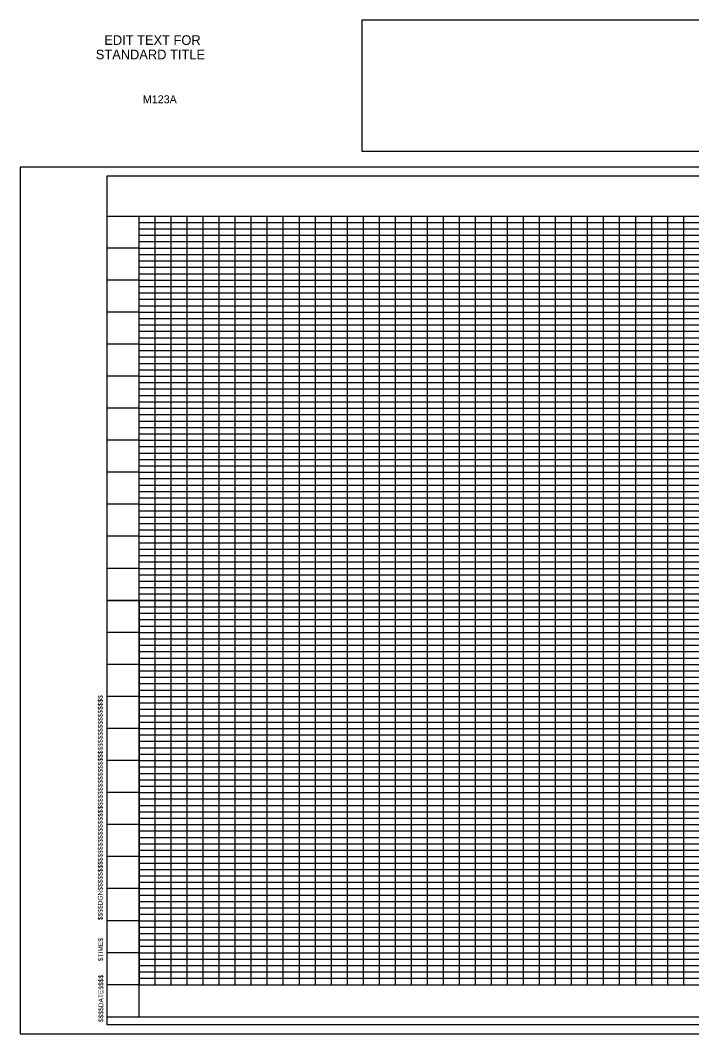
# Model space of a CAD drawing. Extents: x -27 to 395, y -3 to 314.
# Drawn here: x -27.1 to 182.5, y -2.8 to 313.6 of the extents above; entities that cross this region are included whole.
import ezdxf

# ---------------------------------------------------------------- set-up
doc = ezdxf.new("R2010")
doc.units = 0
for name, color, linetype in [('D_CFL_Clip_Boundary_1', 7, 'Continuous'), ('D_CFL_Clip_Boundary_2', 7, 'Continuous'), ('D_CFL_Sheet_Border_ PlotShape', 7, 'Continuous'), ('D_CFL_Sheet_Border_Base', 7, 'Continuous'), ('D_CFL_Sheet_Border_Plan_Plan', 7, 'Continuous'), ('D_CFL_Sheet_Border_PnP', 7, 'Continuous'), ('D_CFL_Sheet_Border_Profile', 7, 'Continuous')]:
    doc.layers.add(name, color=color, linetype=linetype)

msp = doc.modelspace()

# ---------------------------------------------------------------- linework, layer by layer
at = {"layer": 'D_CFL_Clip_Boundary_1'}
msp.add_lwpolyline([(0, 265), (326.25, 265), (326.25, 255), (390, 255), (390, 132.5), (0, 132.5)], close=True, dxfattribs=at)
at = {"layer": 'D_CFL_Clip_Boundary_2'}
msp.add_lwpolyline([(380, 132.5), (10, 132.5), (10, 12.5), (380, 12.5)], close=True, dxfattribs=at)
at = {"layer": 'D_CFL_Sheet_Border_ PlotShape'}
msp.add_line((-27.13, -2.8), (-27.13, -2.8), dxfattribs=at)
msp.add_lwpolyline([(-27.13, -2.8), (395.49, -2.8), (395.49, 267.8), (-27.13, 267.8)], close=True, dxfattribs=at)
at = {"layer": 'D_CFL_Sheet_Border_Base'}
for points in [[(79.54, 272.77), (390, 272.77), (390, 313.62), (79.54, 313.62)], [(0, 265), (390, 265), (390, 0), (0, 0)]]:
    msp.add_lwpolyline(points, close=True, dxfattribs=at)
at = {"layer": 'D_CFL_Sheet_Border_Plan_Plan'}
msp.add_line((0, 132.5), (390, 132.5), dxfattribs=at)
at = {"layer": 'D_CFL_Sheet_Border_PnP'}
for p, q in [((0, 132.5), (390, 132.5)), ((10, 2.5), (10, 132.5)), ((10, 130.5), (380, 130.5)), ((15, 12.5), (15, 132.5)), ((20, 12.5), (20, 132.5)), ((25, 12.5), (25, 132.5)), ((30, 12.5), (30, 132.5)), ((35, 12.5), (35, 132.5)), ((40, 12.5), (40, 132.5)), ((45, 12.5), (45, 132.5)), ((50, 12.5), (50, 132.5)), ((55, 12.5), (55, 132.5)), ((60, 12.5), (60, 132.5)), ((65, 12.5), (65, 132.5)), ((70, 12.5), (70, 132.5)), ((75, 12.5), (75, 132.5)), ((80, 12.5), (80, 132.5)), ((85, 12.5), (85, 132.5)), ((90, 12.5), (90, 132.5)), ((95, 12.5), (95, 132.5)), ((100, 12.5), (100, 132.5)), ((105, 12.5), (105, 132.5)), ((110, 12.5), (110, 132.5)), ((115, 12.5), (115, 132.5)), ((120, 12.5), (120, 132.5)), ((125, 12.5), (125, 132.5)), ((130, 12.5), (130, 132.5)), ((135, 12.5), (135, 132.5)), ((140, 12.5), (140, 132.5)), ((145, 12.5), (145, 132.5)), ((150, 12.5), (150, 132.5)), ((155, 12.5), (155, 132.5)), ((160, 12.5), (160, 132.5)), ((165, 12.5), (165, 132.5)), ((170, 12.5), (170, 132.5)), ((175, 12.5), (175, 132.5)), ((180, 12.5), (180, 132.5)), ((10, 128.5), (380, 128.5)), ((10, 126.5), (380, 126.5)), ((10, 124.5), (380, 124.5)), ((10, 122.5), (0, 122.5)), ((10, 122.5), (380, 122.5)), ((10, 120.5), (380, 120.5)), ((10, 118.5), (380, 118.5)), ((10, 116.5), (380, 116.5)), ((10, 114.5), (380, 114.5)), ((10, 112.5), (0, 112.5)), ((10, 112.5), (380, 112.5)), ((10, 110.5), (380, 110.5)), ((10, 108.5), (380, 108.5)), ((10, 106.5), (380, 106.5)), ((10, 104.5), (380, 104.5)), ((10, 102.5), (0, 102.5)), ((10, 102.5), (380, 102.5)), ((10, 100.5), (380, 100.5)), ((10, 98.5), (380, 98.5)), ((10, 96.5), (380, 96.5)), ((10, 92.5), (0, 92.5)), ((10, 94.5), (380, 94.5)), ((10, 92.5), (380, 92.5)), ((10, 90.5), (380, 90.5)), ((10, 88.5), (380, 88.5)), ((10, 86.5), (380, 86.5)), ((10, 82.5), (0, 82.5)), ((10, 84.5), (380, 84.5)), ((10, 82.5), (380, 82.5)), ((10, 80.5), (380, 80.5)), ((10, 78.5), (380, 78.5)), ((10, 76.5), (380, 76.5)), ((10, 74.5), (380, 74.5)), ((10, 72.5), (0, 72.5)), ((10, 72.5), (380, 72.5)), ((10, 70.5), (380, 70.5)), ((10, 68.5), (380, 68.5)), ((10, 66.5), (380, 66.5)), ((10, 64.5), (380, 64.5)), ((10, 62.5), (0, 62.5)), ((10, 62.5), (380, 62.5)), ((10, 60.5), (380, 60.5)), ((10, 58.5), (380, 58.5)), ((10, 56.5), (380, 56.5)), ((10, 54.5), (380, 54.5)), ((10, 52.5), (0, 52.5)), ((10, 52.5), (380, 52.5)), ((10, 50.5), (380, 50.5)), ((10, 48.5), (380, 48.5)), ((10, 46.5), (380, 46.5)), ((10, 44.5), (380, 44.5)), ((10, 42.5), (0, 42.5)), ((10, 42.5), (380, 42.5)), ((10, 40.5), (380, 40.5)), ((10, 38.5), (380, 38.5)), ((10, 36.5), (380, 36.5)), ((10, 32.5), (0, 32.5)), ((10, 34.5), (380, 34.5)), ((10, 32.5), (380, 32.5)), ((10, 30.5), (380, 30.5)), ((10, 28.5), (380, 28.5)), ((10, 26.5), (380, 26.5)), ((10, 22.5), (0, 22.5)), ((10, 24.5), (380, 24.5)), ((10, 22.5), (380, 22.5)), ((10, 20.5), (380, 20.5)), ((10, 18.5), (380, 18.5)), ((10, 16.5), (380, 16.5)), ((10, 14.5), (380, 14.5)), ((10, 12.5), (0, 12.5)), ((10, 12.5), (380, 12.5)), ((0, 2.5), (390, 2.5))]:
    msp.add_line(p, q, dxfattribs=at)
at = {"layer": 'D_CFL_Sheet_Border_Profile'}
for p, q in [((0, 252.5), (390, 252.5)), ((10, 2.5), (10, 252.5)), ((10, 250.5), (380, 250.5)), ((15, 12.5), (15, 252.5)), ((20, 12.5), (20, 252.5)), ((25, 12.5), (25, 252.5)), ((30, 12.5), (30, 252.5)), ((35, 12.5), (35, 252.5)), ((40, 12.5), (40, 252.5)), ((45, 12.5), (45, 252.5)), ((50, 12.5), (50, 252.5)), ((55, 12.5), (55, 252.5)), ((60, 12.5), (60, 252.5)), ((65, 12.5), (65, 252.5)), ((70, 12.5), (70, 252.5)), ((75, 12.5), (75, 252.5)), ((80, 12.5), (80, 252.5)), ((85, 12.5), (85, 252.5)), ((90, 12.5), (90, 252.5)), ((95, 12.5), (95, 252.5)), ((100, 12.5), (100, 252.5)), ((105, 12.5), (105, 252.5)), ((110, 12.5), (110, 252.5)), ((115, 12.5), (115, 252.5)), ((120, 12.5), (120, 252.5)), ((125, 12.5), (125, 252.5)), ((130, 12.5), (130, 252.5)), ((135, 12.5), (135, 252.5)), ((140, 12.5), (140, 252.5)), ((145, 12.5), (145, 252.5)), ((150, 12.5), (150, 252.5)), ((155, 12.5), (155, 252.5)), ((160, 12.5), (160, 252.5)), ((165, 12.5), (165, 252.5)), ((170, 12.5), (170, 252.5)), ((175, 12.5), (175, 252.5)), ((180, 12.5), (180, 252.5)), ((10, 248.5), (380, 248.5)), ((10, 246.5), (380, 246.5)), ((10, 244.5), (380, 244.5)), ((10, 242.5), (0, 242.5)), ((10, 242.5), (380, 242.5)), ((10, 240.5), (380, 240.5)), ((10, 238.5), (380, 238.5)), ((10, 236.5), (380, 236.5)), ((10, 234.5), (380, 234.5)), ((10, 232.5), (0, 232.5)), ((10, 232.5), (380, 232.5)), ((10, 230.5), (380, 230.5)), ((10, 228.5), (380, 228.5)), ((10, 226.5), (380, 226.5)), ((10, 222.5), (0, 222.5)), ((10, 224.5), (380, 224.5)), ((10, 222.5), (380, 222.5)), ((10, 220.5), (380, 220.5)), ((10, 218.5), (380, 218.5)), ((10, 216.5), (380, 216.5)), ((10, 212.5), (0, 212.5)), ((10, 214.5), (380, 214.5)), ((10, 212.5), (380, 212.5)), ((10, 210.5), (380, 210.5)), ((10, 208.5), (380, 208.5)), ((10, 206.5), (380, 206.5)), ((10, 204.5), (380, 204.5)), ((10, 202.5), (0, 202.5)), ((10, 202.5), (380, 202.5)), ((10, 200.5), (380, 200.5)), ((10, 198.5), (380, 198.5)), ((10, 196.5), (380, 196.5)), ((10, 194.5), (380, 194.5)), ((10, 192.5), (0, 192.5)), ((10, 192.5), (380, 192.5)), ((10, 190.5), (380, 190.5)), ((10, 188.5), (380, 188.5)), ((10, 186.5), (380, 186.5)), ((10, 184.5), (380, 184.5)), ((10, 182.5), (0, 182.5)), ((10, 182.5), (380, 182.5)), ((10, 180.5), (380, 180.5)), ((10, 178.5), (380, 178.5)), ((10, 176.5), (380, 176.5)), ((10, 174.5), (380, 174.5)), ((10, 172.5), (0, 172.5)), ((10, 172.5), (380, 172.5)), ((10, 170.5), (380, 170.5)), ((10, 168.5), (380, 168.5)), ((10, 166.5), (380, 166.5)), ((10, 162.5), (0, 162.5)), ((10, 164.5), (380, 164.5)), ((10, 162.5), (380, 162.5)), ((10, 160.5), (380, 160.5)), ((10, 158.5), (380, 158.5)), ((10, 156.5), (380, 156.5)), ((10, 152.5), (0, 152.5)), ((10, 154.5), (380, 154.5)), ((10, 152.5), (380, 152.5)), ((10, 150.5), (380, 150.5)), ((10, 148.5), (380, 148.5)), ((10, 146.5), (380, 146.5)), ((10, 142.5), (0, 142.5)), ((10, 144.5), (380, 144.5)), ((10, 142.5), (380, 142.5)), ((10, 140.5), (380, 140.5)), ((10, 138.5), (380, 138.5)), ((10, 136.5), (380, 136.5)), ((10, 134.5), (380, 134.5)), ((10, 132.5), (0, 132.5)), ((10, 132.5), (380, 132.5)), ((10, 130.5), (380, 130.5)), ((10, 128.5), (380, 128.5)), ((10, 126.5), (380, 126.5)), ((10, 124.5), (380, 124.5)), ((10, 122.5), (0, 122.5)), ((10, 122.5), (380, 122.5)), ((10, 120.5), (380, 120.5)), ((10, 118.5), (380, 118.5)), ((10, 116.5), (380, 116.5)), ((10, 114.5), (380, 114.5)), ((10, 112.5), (0, 112.5)), ((10, 112.5), (380, 112.5)), ((10, 110.5), (380, 110.5)), ((10, 108.5), (380, 108.5)), ((10, 106.5), (380, 106.5)), ((10, 104.5), (380, 104.5)), ((10, 102.5), (0, 102.5)), ((10, 102.5), (380, 102.5)), ((10, 100.5), (380, 100.5)), ((10, 98.5), (380, 98.5)), ((10, 96.5), (380, 96.5)), ((10, 92.5), (0, 92.5)), ((10, 94.5), (380, 94.5)), ((10, 92.5), (380, 92.5)), ((10, 90.5), (380, 90.5)), ((10, 88.5), (380, 88.5)), ((10, 86.5), (380, 86.5)), ((10, 82.5), (0, 82.5)), ((10, 84.5), (380, 84.5)), ((10, 82.5), (380, 82.5)), ((10, 80.5), (380, 80.5)), ((10, 78.5), (380, 78.5)), ((10, 76.5), (380, 76.5)), ((10, 74.5), (380, 74.5)), ((10, 72.5), (0, 72.5)), ((10, 72.5), (380, 72.5)), ((10, 70.5), (380, 70.5)), ((10, 68.5), (380, 68.5)), ((10, 66.5), (380, 66.5)), ((10, 64.5), (380, 64.5)), ((10, 62.5), (0, 62.5)), ((10, 62.5), (380, 62.5)), ((10, 60.5), (380, 60.5)), ((10, 58.5), (380, 58.5)), ((10, 56.5), (380, 56.5)), ((10, 54.5), (380, 54.5)), ((10, 52.5), (0, 52.5)), ((10, 52.5), (380, 52.5)), ((10, 50.5), (380, 50.5)), ((10, 48.5), (380, 48.5)), ((10, 46.5), (380, 46.5)), ((10, 44.5), (380, 44.5)), ((10, 42.5), (0, 42.5)), ((10, 42.5), (380, 42.5)), ((10, 40.5), (380, 40.5)), ((10, 38.5), (380, 38.5)), ((10, 36.5), (380, 36.5)), ((10, 32.5), (0, 32.5)), ((10, 34.5), (380, 34.5)), ((10, 32.5), (380, 32.5)), ((10, 30.5), (380, 30.5)), ((10, 28.5), (380, 28.5)), ((10, 26.5), (380, 26.5)), ((10, 22.5), (0, 22.5)), ((10, 24.5), (380, 24.5)), ((10, 22.5), (380, 22.5)), ((10, 20.5), (380, 20.5)), ((10, 18.5), (380, 18.5)), ((10, 16.5), (380, 16.5)), ((10, 14.5), (380, 14.5)), ((10, 12.5), (0, 12.5)), ((10, 12.5), (380, 12.5)), ((0, 2.5), (390, 2.5))]:
    msp.add_line(p, q, dxfattribs=at)

# ---------------------------------------------------------------- texts
at = {"layer": 'D_CFL_Sheet_Border_Base'}
for s, height, p in [('EDIT TEXT FOR', 3, (-0.89, 305.93)), ('STANDARD TITLE', 3, (-3.55, 301.43)), ('M123A', 2.5, (11.14, 287.68))]:
    msp.add_text(s, height=height, dxfattribs=at).set_placement(p)
for s, p in [('$$$$DGN$$$$$$$$$$$$$$$$$$$$$$$$$$$$$$$$$$$$$$$$$$$$$$$$$$$$$', (-1.4, 32.65)), ('$TIME$', (-1.3, 19.83)), ('$$$$DATE$$$$', (-1.2, 0.85))]:
    msp.add_text(s, height=1.5, rotation=90, dxfattribs=at).set_placement(p)

doc.saveas('drawing.dxf')
